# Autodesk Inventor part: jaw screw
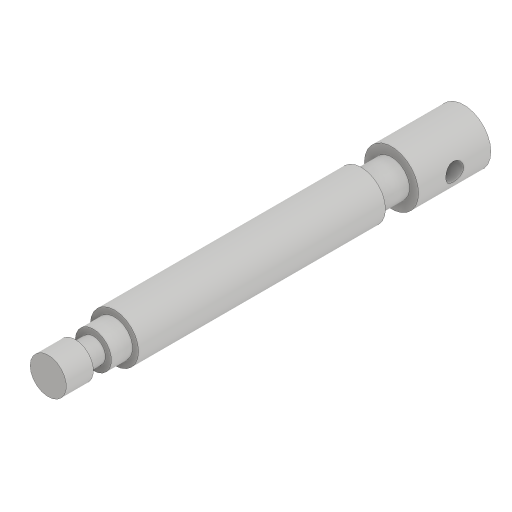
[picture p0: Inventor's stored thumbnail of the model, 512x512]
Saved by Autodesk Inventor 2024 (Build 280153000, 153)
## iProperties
Created: 2016-03
Part Number: jaw screw
Material: Generic
Document SubType Name: Modeling
Designer: Sandeep
Density: 1 g/cm^3
Appearance: Default
Mass: 25.5852 g
Surface Area: 75.8462 cm^2
Volume: 25.5852 cm^3
Author: Sandeep
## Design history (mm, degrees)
sketch "Sketch1"
  geometry: L1 (0, -138)-(-6, -138); L2 (-6, -116)-(-6, -116); L3 (-6, -116)-(-8, -116); L4 (-8, -116)-(-8, -34); L5 (-8, -34)-(-6, -34); L6 (-6, -34)-(-6, -24); L7 (-6, -24)-(-9, -24); L8 (-9, -24)-(-9, 0); L9 (-9, 0)-(0, 0); L10 (0, 0)-(0, -138); L11 (0, 0)-(0, 14.581); L12 (-6, -116)-(-6, -123); L13 (-6, -123)-(-4, -123); L14 (-4, -123)-(-4, -129); L15 (-4, -129)-(-6, -129); L16 (-6, -129)-(-6, -138); 1 other entity
  constraints: 32 end point, 10 perpendicular, 3 point on line, 3 vertical, 1 coincident, 1 horizontal, 2 other
  dimensions: "d0" = 18 diameter of L8 L11; "d1" = 12 diameter of L6 L11; "d3" = 24 distance of L7.end L8.end; "d4" = 10 distance of L5.end L6.end; "d5" = 82 distance of L3.end L4.end; "d6" = 138 distance between parallel lines of L1 L9; "d8" = 16 diameter of L4 L11; "d10" = 6 distance of L13.end L14.end; "d11" = 9 distance of L15.end L1.end; "d12" = 8 diameter of L14 L11
revolve "Revolution1" sketch "Sketch1" stored, may be unused: angle "d9" = 90 deg
sketch "Sketch2"
  geometry: L1 (0, -9)-(0, 9) reference; L2 (0, 0)-(-20.975, 0); C1 r 3 at (-12, 0)
  constraints: 2 end point, 1 centre point, 1 horizontal, 1 point on line
  dimensions: "d13" = 6 diameter of C1; "d14" = 12 distance from line of L1 C1.centre
extrude "Extrusion1" cut sketch "Sketch2" distance "d15" = 25; taper "d16" = 0 deg
body "Solid1"
